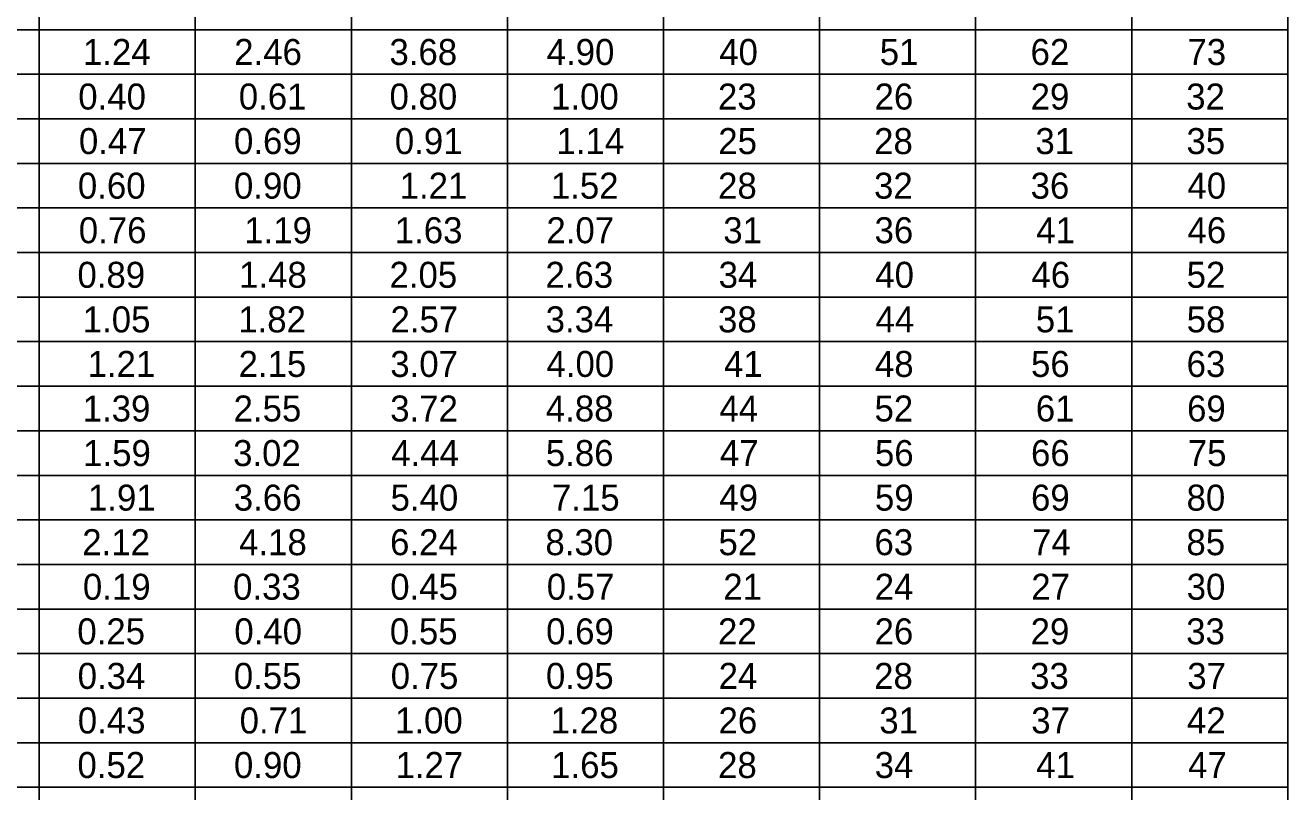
# Model space of a CAD drawing. Extents: x -1.3 to 14.6, y 0 to 8.4.
# Drawn here: x 10.062 to 13.46, y 4.218 to 6.282 of the extents above; entities that cross this region are included whole.
import ezdxf

# ---------------------------------------------------------------- set-up
doc = ezdxf.new("R2010")
doc.units = 0
doc.layers.add('Table', color=7, linetype='Continuous')

msp = doc.modelspace()

# ---------------------------------------------------------------- linework, layer by layer
at = {"layer": 'Table'}
for points in [[(10.1, 6.39), (10.1, 6.27), (10.1, 6.15), (10.1, 6.03), (10.1, 5.91), (10.1, 5.79), (10.1, 5.67), (10.1, 5.55), (10.1, 5.43), (10.1, 5.31), (10.1, 5.19), (10.1, 5.07), (10.1, 4.95), (10.1, 4.83), (10.1, 4.71), (10.1, 4.59), (10.1, 4.47), (10.1, 4.35), (10.1, 4.23), (10.1, 4.11)], [(10.52, 6.39), (10.52, 6.27), (10.52, 6.15), (10.52, 6.03), (10.52, 5.91), (10.52, 5.79), (10.52, 5.67), (10.52, 5.55), (10.52, 5.43), (10.52, 5.31), (10.52, 5.19), (10.52, 5.07), (10.52, 4.95), (10.52, 4.83), (10.52, 4.71), (10.52, 4.59), (10.52, 4.47), (10.52, 4.35), (10.52, 4.23), (10.52, 4.11)], [(10.94, 6.39), (10.94, 6.27), (10.94, 6.15), (10.94, 6.03), (10.94, 5.91), (10.94, 5.79), (10.94, 5.67), (10.94, 5.55), (10.94, 5.43), (10.94, 5.31), (10.94, 5.19), (10.94, 5.07), (10.94, 4.95), (10.94, 4.83), (10.94, 4.71), (10.94, 4.59), (10.94, 4.47), (10.94, 4.35), (10.94, 4.23), (10.94, 4.11)], [(11.36, 6.39), (11.36, 6.27), (11.36, 6.15), (11.36, 6.03), (11.36, 5.91), (11.36, 5.79), (11.36, 5.67), (11.36, 5.55), (11.36, 5.43), (11.36, 5.31), (11.36, 5.19), (11.36, 5.07), (11.36, 4.95), (11.36, 4.83), (11.36, 4.71), (11.36, 4.59), (11.36, 4.47), (11.36, 4.35), (11.36, 4.23), (11.36, 4.11)], [(11.78, 6.39), (11.78, 6.27), (11.78, 6.15), (11.78, 6.03), (11.78, 5.91), (11.78, 5.79), (11.78, 5.67), (11.78, 5.55), (11.78, 5.43), (11.78, 5.31), (11.78, 5.19), (11.78, 5.07), (11.78, 4.95), (11.78, 4.83), (11.78, 4.71), (11.78, 4.59), (11.78, 4.47), (11.78, 4.35), (11.78, 4.23), (11.78, 4.11)], [(12.2, 6.39), (12.2, 6.27), (12.2, 6.15), (12.2, 6.03), (12.2, 5.91), (12.2, 5.79), (12.2, 5.67), (12.2, 5.55), (12.2, 5.43), (12.2, 5.31), (12.2, 5.19), (12.2, 5.07), (12.2, 4.95), (12.2, 4.83), (12.2, 4.71), (12.2, 4.59), (12.2, 4.47), (12.2, 4.35), (12.2, 4.23), (12.2, 4.11)], [(12.62, 6.39), (12.62, 6.27), (12.62, 6.15), (12.62, 6.03), (12.62, 5.91), (12.62, 5.79), (12.62, 5.67), (12.62, 5.55), (12.62, 5.43), (12.62, 5.31), (12.62, 5.19), (12.62, 5.07), (12.62, 4.95), (12.62, 4.83), (12.62, 4.71), (12.62, 4.59), (12.62, 4.47), (12.62, 4.35), (12.62, 4.23), (12.62, 4.11)], [(13.04, 6.39), (13.04, 6.27), (13.04, 6.15), (13.04, 6.03), (13.04, 5.91), (13.04, 5.79), (13.04, 5.67), (13.04, 5.55), (13.04, 5.43), (13.04, 5.31), (13.04, 5.19), (13.04, 5.07), (13.04, 4.95), (13.04, 4.83), (13.04, 4.71), (13.04, 4.59), (13.04, 4.47), (13.04, 4.35), (13.04, 4.23), (13.04, 4.11)], [(13.46, 6.39), (13.46, 6.27), (13.46, 6.15), (13.46, 6.03), (13.46, 5.91), (13.46, 5.79), (13.46, 5.67), (13.46, 5.55), (13.46, 5.43), (13.46, 5.31), (13.46, 5.19), (13.46, 5.07), (13.46, 4.95), (13.46, 4.83), (13.46, 4.71), (13.46, 4.59), (13.46, 4.47), (13.46, 4.35), (13.46, 4.23), (13.46, 4.11)], [(4.04, 6.27), (4.52, 6.27), (4.94, 6.27), (5.42, 6.27), (5.66, 6.27), (6.02, 6.27), (6.38, 6.27), (6.8, 6.27), (7.22, 6.27), (7.64, 6.27), (8.06, 6.27), (8.42, 6.27), (8.84, 6.27), (9.26, 6.27), (9.68, 6.27), (10.1, 6.27), (10.52, 6.27), (10.94, 6.27), (11.36, 6.27), (11.78, 6.27), (12.2, 6.27), (12.62, 6.27), (13.04, 6.27), (13.46, 6.27)], [(4.04, 6.15), (4.52, 6.15), (4.94, 6.15), (5.42, 6.15), (5.66, 6.15), (6.02, 6.15), (6.38, 6.15), (6.8, 6.15), (7.22, 6.15), (7.64, 6.15), (8.06, 6.15), (8.42, 6.15), (8.84, 6.15), (9.26, 6.15), (9.68, 6.15), (10.1, 6.15), (10.52, 6.15), (10.94, 6.15), (11.36, 6.15), (11.78, 6.15), (12.2, 6.15), (12.62, 6.15), (13.04, 6.15), (13.46, 6.15)], [(4.04, 6.03), (4.52, 6.03), (4.94, 6.03), (5.42, 6.03), (5.66, 6.03), (6.02, 6.03), (6.38, 6.03), (6.8, 6.03), (7.22, 6.03), (7.64, 6.03), (8.06, 6.03), (8.42, 6.03), (8.84, 6.03), (9.26, 6.03), (9.68, 6.03), (10.1, 6.03), (10.52, 6.03), (10.94, 6.03), (11.36, 6.03), (11.78, 6.03), (12.2, 6.03), (12.62, 6.03), (13.04, 6.03), (13.46, 6.03)], [(4.04, 5.91), (4.52, 5.91), (4.94, 5.91), (5.42, 5.91), (5.66, 5.91), (6.02, 5.91), (6.38, 5.91), (6.8, 5.91), (7.22, 5.91), (7.64, 5.91), (8.06, 5.91), (8.42, 5.91), (8.84, 5.91), (9.26, 5.91), (9.68, 5.91), (10.1, 5.91), (10.52, 5.91), (10.94, 5.91), (11.36, 5.91), (11.78, 5.91), (12.2, 5.91), (12.62, 5.91), (13.04, 5.91), (13.46, 5.91)], [(4.04, 5.79), (4.52, 5.79), (4.94, 5.79), (5.42, 5.79), (5.66, 5.79), (6.02, 5.79), (6.38, 5.79), (6.8, 5.79), (7.22, 5.79), (7.64, 5.79), (8.06, 5.79), (8.42, 5.79), (8.84, 5.79), (9.26, 5.79), (9.68, 5.79), (10.1, 5.79), (10.52, 5.79), (10.94, 5.79), (11.36, 5.79), (11.78, 5.79), (12.2, 5.79), (12.62, 5.79), (13.04, 5.79), (13.46, 5.79)], [(4.04, 5.67), (4.52, 5.67), (4.94, 5.67), (5.42, 5.67), (5.66, 5.67), (6.02, 5.67), (6.38, 5.67), (6.8, 5.67), (7.22, 5.67), (7.64, 5.67), (8.06, 5.67), (8.42, 5.67), (8.84, 5.67), (9.26, 5.67), (9.68, 5.67), (10.1, 5.67), (10.52, 5.67), (10.94, 5.67), (11.36, 5.67), (11.78, 5.67), (12.2, 5.67), (12.62, 5.67), (13.04, 5.67), (13.46, 5.67)], [(4.04, 5.55), (4.52, 5.55), (4.94, 5.55), (5.42, 5.55), (5.66, 5.55), (6.02, 5.55), (6.38, 5.55), (6.8, 5.55), (7.22, 5.55), (7.64, 5.55), (8.06, 5.55), (8.42, 5.55), (8.84, 5.55), (9.26, 5.55), (9.68, 5.55), (10.1, 5.55), (10.52, 5.55), (10.94, 5.55), (11.36, 5.55), (11.78, 5.55), (12.2, 5.55), (12.62, 5.55), (13.04, 5.55), (13.46, 5.55)], [(4.04, 5.43), (4.52, 5.43), (4.94, 5.43), (5.42, 5.43), (5.66, 5.43), (6.02, 5.43), (6.38, 5.43), (6.8, 5.43), (7.22, 5.43), (7.64, 5.43), (8.06, 5.43), (8.42, 5.43), (8.84, 5.43), (9.26, 5.43), (9.68, 5.43), (10.1, 5.43), (10.52, 5.43), (10.94, 5.43), (11.36, 5.43), (11.78, 5.43), (12.2, 5.43), (12.62, 5.43), (13.04, 5.43), (13.46, 5.43)], [(4.04, 5.31), (4.52, 5.31), (4.94, 5.31), (5.42, 5.31), (5.66, 5.31), (6.02, 5.31), (6.38, 5.31), (6.8, 5.31), (7.22, 5.31), (7.64, 5.31), (8.06, 5.31), (8.42, 5.31), (8.84, 5.31), (9.26, 5.31), (9.68, 5.31), (10.1, 5.31), (10.52, 5.31), (10.94, 5.31), (11.36, 5.31), (11.78, 5.31), (12.2, 5.31), (12.62, 5.31), (13.04, 5.31), (13.46, 5.31)], [(4.04, 5.19), (4.52, 5.19), (4.94, 5.19), (5.42, 5.19), (5.66, 5.19), (6.02, 5.19), (6.38, 5.19), (6.8, 5.19), (7.22, 5.19), (7.64, 5.19), (8.06, 5.19), (8.42, 5.19), (8.84, 5.19), (9.26, 5.19), (9.68, 5.19), (10.1, 5.19), (10.52, 5.19), (10.94, 5.19), (11.36, 5.19), (11.78, 5.19), (12.2, 5.19), (12.62, 5.19), (13.04, 5.19), (13.46, 5.19)], [(4.04, 5.07), (4.52, 5.07), (4.94, 5.07), (5.42, 5.07), (5.66, 5.07), (6.02, 5.07), (6.38, 5.07), (6.8, 5.07), (7.22, 5.07), (7.64, 5.07), (8.06, 5.07), (8.42, 5.07), (8.84, 5.07), (9.26, 5.07), (9.68, 5.07), (10.1, 5.07), (10.52, 5.07), (10.94, 5.07), (11.36, 5.07), (11.78, 5.07), (12.2, 5.07), (12.62, 5.07), (13.04, 5.07), (13.46, 5.07)], [(4.04, 4.95), (4.52, 4.95), (4.94, 4.95), (5.42, 4.95), (5.66, 4.95), (6.02, 4.95), (6.38, 4.95), (6.8, 4.95), (7.22, 4.95), (7.64, 4.95), (8.06, 4.95), (8.42, 4.95), (8.84, 4.95), (9.26, 4.95), (9.68, 4.95), (10.1, 4.95), (10.52, 4.95), (10.94, 4.95), (11.36, 4.95), (11.78, 4.95), (12.2, 4.95), (12.62, 4.95), (13.04, 4.95), (13.46, 4.95)], [(4.04, 4.83), (4.52, 4.83), (4.94, 4.83), (5.42, 4.83), (5.66, 4.83), (6.02, 4.83), (6.38, 4.83), (6.8, 4.83), (7.22, 4.83), (7.64, 4.83), (8.06, 4.83), (8.42, 4.83), (8.84, 4.83), (9.26, 4.83), (9.68, 4.83), (10.1, 4.83), (10.52, 4.83), (10.94, 4.83), (11.36, 4.83), (11.78, 4.83), (12.2, 4.83), (12.62, 4.83), (13.04, 4.83), (13.46, 4.83)], [(4.04, 4.71), (4.52, 4.71), (4.94, 4.71), (5.42, 4.71), (5.66, 4.71), (6.02, 4.71), (6.38, 4.71), (6.8, 4.71), (7.22, 4.71), (7.64, 4.71), (8.06, 4.71), (8.42, 4.71), (8.84, 4.71), (9.26, 4.71), (9.68, 4.71), (10.1, 4.71), (10.52, 4.71), (10.94, 4.71), (11.36, 4.71), (11.78, 4.71), (12.2, 4.71), (12.62, 4.71), (13.04, 4.71), (13.46, 4.71)], [(4.04, 4.59), (4.52, 4.59), (4.94, 4.59), (5.42, 4.59), (5.66, 4.59), (6.02, 4.59), (6.38, 4.59), (6.8, 4.59), (7.22, 4.59), (7.64, 4.59), (8.06, 4.59), (8.42, 4.59), (8.84, 4.59), (9.26, 4.59), (9.68, 4.59), (10.1, 4.59), (10.52, 4.59), (10.94, 4.59), (11.36, 4.59), (11.78, 4.59), (12.2, 4.59), (12.62, 4.59), (13.04, 4.59), (13.46, 4.59)], [(4.04, 4.47), (4.52, 4.47), (4.94, 4.47), (5.42, 4.47), (5.66, 4.47), (6.02, 4.47), (6.38, 4.47), (6.8, 4.47), (7.22, 4.47), (7.64, 4.47), (8.06, 4.47), (8.42, 4.47), (8.84, 4.47), (9.26, 4.47), (9.68, 4.47), (10.1, 4.47), (10.52, 4.47), (10.94, 4.47), (11.36, 4.47), (11.78, 4.47), (12.2, 4.47), (12.62, 4.47), (13.04, 4.47), (13.46, 4.47)], [(4.04, 4.35), (4.52, 4.35), (4.94, 4.35), (5.42, 4.35), (5.66, 4.35), (6.02, 4.35), (6.38, 4.35), (6.8, 4.35), (7.22, 4.35), (7.64, 4.35), (8.06, 4.35), (8.42, 4.35), (8.84, 4.35), (9.26, 4.35), (9.68, 4.35), (10.1, 4.35), (10.52, 4.35), (10.94, 4.35), (11.36, 4.35), (11.78, 4.35), (12.2, 4.35), (12.62, 4.35), (13.04, 4.35), (13.46, 4.35)], [(4.04, 4.23), (4.52, 4.23), (4.94, 4.23), (5.42, 4.23), (5.66, 4.23), (6.02, 4.23), (6.38, 4.23), (6.8, 4.23), (7.22, 4.23), (7.64, 4.23), (8.06, 4.23), (8.42, 4.23), (8.84, 4.23), (9.26, 4.23), (9.68, 4.23), (10.1, 4.23), (10.52, 4.23), (10.94, 4.23), (11.36, 4.23), (11.78, 4.23), (12.2, 4.23), (12.62, 4.23), (13.04, 4.23), (13.46, 4.23)]]:
    msp.add_lwpolyline(points, dxfattribs=at)

# ---------------------------------------------------------------- texts
for s, p in [('1.24', (10.2176, 6.175)), ('2.46', (10.6247, 6.175)), ('3.68', (11.0425, 6.175)), ('4.90', (11.4657, 6.175)), ('0.40', (10.2051, 6.055)), ('0.61', (10.6371, 6.055)), ('0.80', (11.0428, 6.055)), ('1.00', (11.4775, 6.055)), ('0.47', (10.2069, 5.935)), ('0.69', (10.6242, 5.935)), ('0.91', (11.0571, 5.935)), ('1.14', (11.4921, 5.935)), ('0.60', (10.2041, 5.815)), ('0.90', (10.6241, 5.815)), ('1.21', (11.07, 5.815)), ('1.52', (11.4769, 5.815)), ('0.76', (10.2065, 5.695)), ('1.19', (10.6516, 5.695)), ('1.63', (11.0568, 5.695)), ('2.07', (11.4649, 5.695)), ('0.89', (10.2029, 5.575)), ('1.48', (10.638, 5.575)), ('2.05', (11.0426, 5.575)), ('2.63', (11.4623, 5.575)), ('1.05', (10.2171, 5.455)), ('1.82', (10.6356, 5.455)), ('2.57', (11.0454, 5.455)), ('3.34', (11.4629, 5.455)), ('1.21', (10.23, 5.335)), ('2.15', (10.6366, 5.335)), ('3.07', (11.0448, 5.335)), ('4.00', (11.4651, 5.335)), ('1.39', (10.217, 5.215)), ('2.55', (10.6231, 5.215)), ('3.72', (11.0446, 5.215)), ('4.88', (11.4633, 5.215)), ('1.59', (10.2182, 5.095)), ('3.02', (10.6218, 5.095)), ('4.44', (11.0472, 5.095)), ('5.86', (11.4634, 5.095)), ('1.91', (10.2311, 4.975)), ('3.66', (10.6236, 4.975)), ('5.40', (11.0456, 4.975)), ('7.15', (11.4799, 4.975)), ('2.12', (10.2158, 4.855)), ('4.18', (10.638, 4.855)), ('6.24', (11.0442, 4.855)), ('8.30', (11.4622, 4.855)), ('0.19', (10.2176, 4.735)), ('0.33', (10.6217, 4.735)), ('0.45', (11.0447, 4.735)), ('0.57', (11.4659, 4.735)), ('0.25', (10.2026, 4.615)), ('0.40', (10.6251, 4.615)), ('0.55', (11.0437, 4.615)), ('0.69', (11.4642, 4.615)), ('0.34', (10.2035, 4.495)), ('0.55', (10.6237, 4.495)), ('0.75', (11.0459, 4.495)), ('0.95', (11.4637, 4.495)), ('0.43', (10.2038, 4.375)), ('0.71', (10.6394, 4.375)), ('1.00', (11.0575, 4.375)), ('1.28', (11.476, 4.375)), ('0.52', (10.2029, 4.255)), ('0.90', (10.6241, 4.255)), ('1.27', (11.0589, 4.255)), ('1.65', (11.4777, 4.255))]:
    msp.add_text(s, height=0.07, dxfattribs=at).set_placement(p)
for s, p in [('40', (11.93, 6.175)), ('51', (12.362, 6.175)), ('62', (12.7679, 6.175)), ('73', (13.19, 6.175)), ('23', (11.9267, 6.055)), ('26', (12.3481, 6.055)), ('29', (12.7681, 6.055)), ('32', (13.1867, 6.055)), ('25', (11.9275, 5.935)), ('28', (12.3469, 5.935)), ('31', (12.7809, 5.935)), ('35', (13.1874, 5.935)), ('28', (11.9269, 5.815)), ('32', (12.3467, 5.815)), ('36', (12.768, 5.815)), ('40', (13.19, 5.815)), ('31', (11.9409, 5.695)), ('36', (12.348, 5.695)), ('41', (12.783, 5.695)), ('46', (13.1901, 5.695)), ('34', (11.9284, 5.575)), ('40', (12.35, 5.575)), ('46', (12.7701, 5.575)), ('52', (13.1879, 5.575)), ('38', (11.9268, 5.455)), ('44', (12.3506, 5.455)), ('51', (12.782, 5.455)), ('58', (13.188, 5.455)), ('41', (11.943, 5.335)), ('48', (12.349, 5.335)), ('56', (12.7691, 5.335)), ('63', (13.1878, 5.335)), ('44', (11.9306, 5.215)), ('52', (12.3479, 5.215)), ('61', (12.782, 5.215)), ('69', (13.1891, 5.215)), ('47', (11.9319, 5.095)), ('56', (12.3491, 5.095)), ('66', (12.7691, 5.095)), ('75', (13.1909, 5.095)), ('49', (11.9301, 4.975)), ('59', (12.3491, 4.975)), ('69', (12.7691, 4.975)), ('80', (13.1877, 4.975)), ('52', (11.9279, 4.855)), ('63', (12.3478, 4.855)), ('74', (12.7719, 4.855)), ('85', (13.1873, 4.855)), ('21', (11.941, 4.735)), ('24', (12.3485, 4.735)), ('27', (12.7698, 4.735)), ('30', (13.1879, 4.735)), ('22', (11.9268, 4.615)), ('26', (12.3481, 4.615)), ('29', (12.7681, 4.615)), ('33', (13.1866, 4.615)), ('24', (11.9285, 4.495)), ('28', (12.3469, 4.495)), ('33', (12.7666, 4.495)), ('37', (13.1897, 4.495)), ('26', (11.9281, 4.375)), ('31', (12.3609, 4.375)), ('37', (12.7697, 4.375)), ('42', (13.1889, 4.375)), ('28', (11.9269, 4.255)), ('34', (12.3484, 4.255)), ('41', (12.783, 4.255)), ('47', (13.1919, 4.255))]:
    msp.add_text(s, height=0.07, rotation=0, dxfattribs=at).set_placement(p)

doc.saveas('drawing.dxf')
